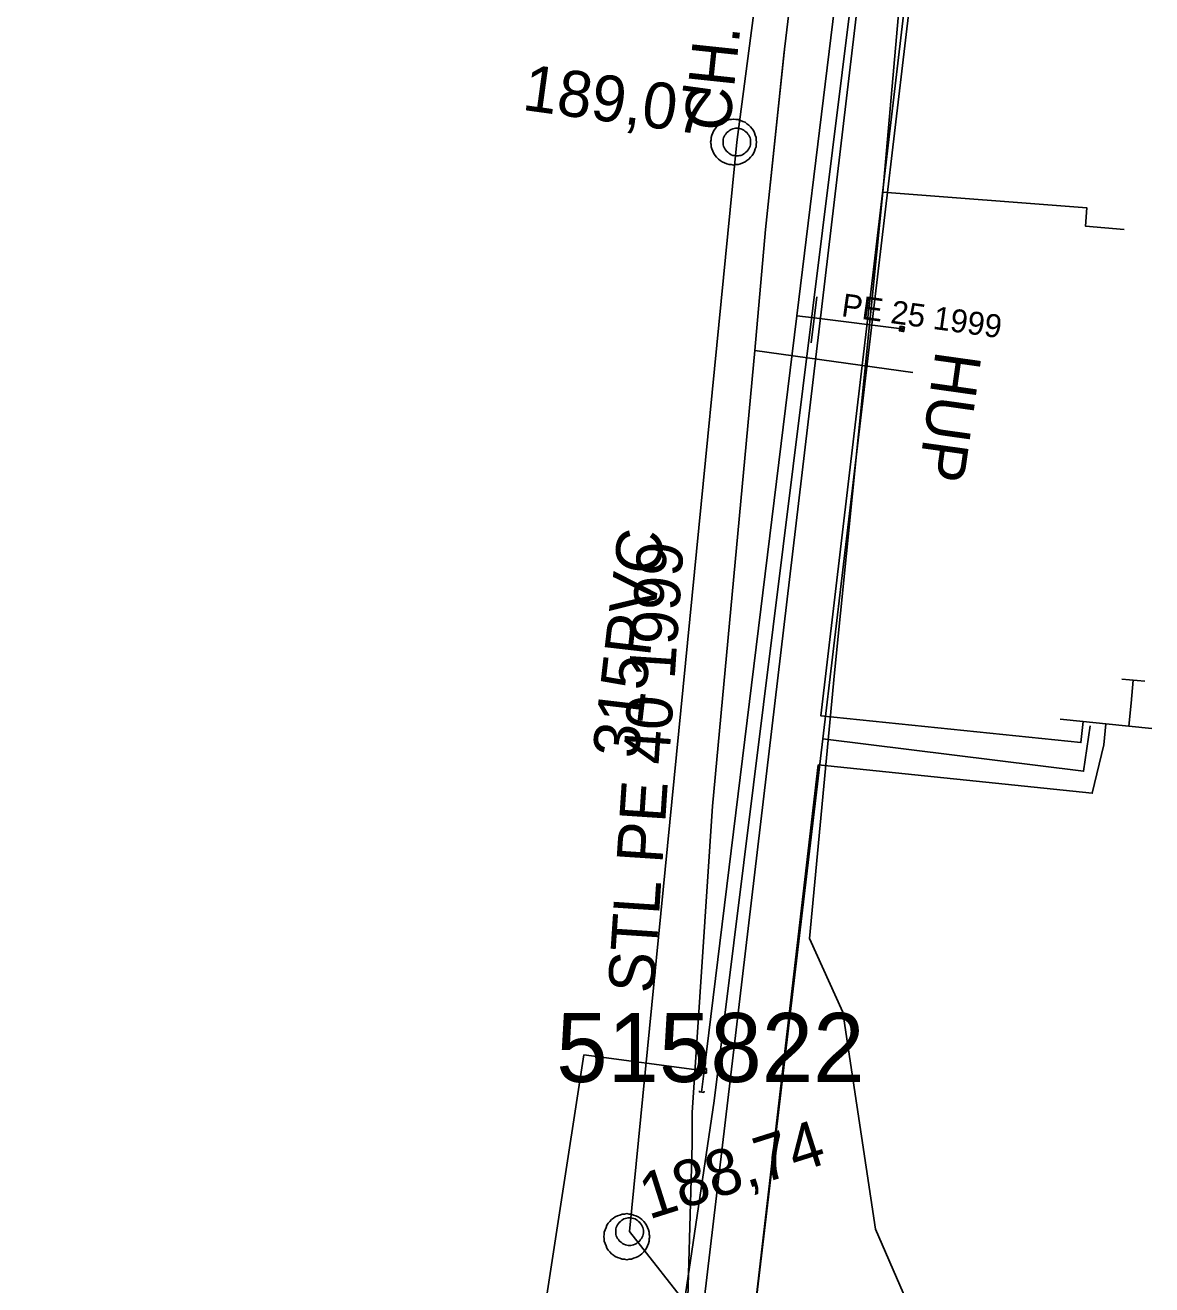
# Model space of a CAD drawing. Extents: x -746464 to -745690, y -1051581 to -1049993.
# Drawn here: x -745945.52 to -745921.06, y -1050962.47 to -1050935.1 of the extents above; entities that cross this region are included whole.
import ezdxf

# ---------------------------------------------------------------- set-up
doc = ezdxf.new("R2010")
doc.units = 0
for name, color, linetype in [('04_CETIN_sdelovaci_podzem', 7, 'Continuous'), ('45_Eltodo_popisy', 7, 'Continuous'), ('45_Eltodo_vedeni_NN_zemni', 7, 'Continuous'), ('48_Prazs_plynarenska_STL', 7, 'Continuous'), ('48_Prazs_plynarenska_STL_chranicka', 7, 'Continuous'), ('48_Prazs_plynarenska_STL_popisy', 7, 'Continuous'), ('51_PVaK_kanal_jednotna_overena poloha_rad', 7, 'Continuous'), ('51_PVaK_kanal_objekty', 7, 'Continuous'), ('51_PVaK_kanal_popisy', 7, 'Continuous'), ('51_PVaK_vodovod_chranicky_objekty', 7, 'Continuous'), ('51_PVaK_vodovod_neoverena poloha_rad', 7, 'Continuous'), ('51_PVaK_vodovod_NEPROVOZUJE PVK_neoverene poloha', 7, 'Continuous'), ('51_PVaK_vodovod_overena poloha_rad', 7, 'Continuous'), ('55_PREdi_NN', 7, 'Continuous'), ('55_PREdi_NN_pripojovaci_misto', 7, 'Continuous')]:
    doc.layers.add(name, color=color, linetype=linetype)

msp = doc.modelspace()

# ---------------------------------------------------------------- linework, layer by layer
at = {"layer": '04_CETIN_sdelovaci_podzem'}
for points in [[(-745926.9, -1050938.73), (-745925.45, -1050922.26), (-745924.92, -1050917.99), (-745924.55, -1050915.62)], [(-745935.44, -1051011.78), (-745933.08, -1050998.46), (-745931.59, -1050985.81), (-745929.11, -1050980.04), (-745927.99, -1050979.19), (-745925.39, -1050979.32), (-745925.27, -1050978.86), (-745922.89, -1050971.35), (-745922.49, -1050970.43), (-745924.73, -1050966.62), (-745927.06, -1050961.26), (-745927.77, -1050956.54), (-745928.49, -1050954.94), (-745927.95, -1050949.17), (-745926.9, -1050938.73)], [(-745926.9, -1050938.73), (-745922.47, -1050939.07), (-745922.5, -1050939.47), (-745921.66, -1050939.54)]]:
    msp.add_lwpolyline(points, dxfattribs=at)
at = {"layer": '45_Eltodo_vedeni_NN_zemni'}
for points in [[(-745930.562, -1050958.466), (-745927.567, -1050934.378)], [(-745933.528, -1050986.207), (-745930.448, -1050965.155), (-745931.301, -1050963.448), (-745930.562, -1050958.466)]]:
    msp.add_lwpolyline(points, dxfattribs=at)
at = {"layer": '48_Prazs_plynarenska_STL'}
for points in [[(-745924.24, -1050897.439), (-745924.39, -1050898.5), (-745926.58, -1050914.43), (-745928.11, -1050927.89), (-745929.03, -1050935.56), (-745929.042, -1050935.678), (-745929.45, -1050939.54), (-745929.68, -1050942.17), (-745930.6, -1050952.07), (-745931.04, -1050958.72), (-745931.04, -1050959.41), (-745931.16, -1050963.77), (-745931.63, -1050972.21), (-745932.22, -1050976.26), (-745932.83, -1050980.22), (-745934.11, -1050987.61), (-745935.84, -1050998.78), (-745937.38, -1051010.18), (-745934.03, -1051011.36), (-745934.04, -1051011.96)], [(-745929.68, -1050942.17), (-745926.248, -1050942.648)]]:
    msp.add_lwpolyline(points, dxfattribs=at)
at = {"layer": '48_Prazs_plynarenska_STL_chranicka'}
msp.add_lwpolyline([(-745929.449, -1050939.539), (-745929.029, -1050935.559)], dxfattribs=at)
at = {"layer": '51_PVaK_kanal_jednotna_overena poloha_rad'}
for p, q in [((-745930.07, -1050937.64), (-745932.4, -1050961.31)), ((-745932.4, -1050961.31), (-745922.1, -1050974.41))]:
    msp.add_line(p, q, dxfattribs=at)
msp.add_lwpolyline([(-745924.23, -1050893.24), (-745924.489, -1050895.205), (-745926.679, -1050911.862), (-745928.844, -1050928.32), (-745930.07, -1050937.64)], dxfattribs=at)
at = {"layer": '51_PVaK_kanal_objekty'}
for points in [[(-745929.64, -1050937.64), (-745929.65, -1050937.59), (-745929.65, -1050937.54), (-745929.67, -1050937.49), (-745929.69, -1050937.44), (-745929.71, -1050937.39), (-745929.74, -1050937.35), (-745929.77, -1050937.31), (-745929.81, -1050937.27), (-745929.85, -1050937.24), (-745929.89, -1050937.21), (-745929.94, -1050937.19), (-745929.99, -1050937.17), (-745930.04, -1050937.15), (-745930.09, -1050937.15), (-745930.14, -1050937.14), (-745930.19, -1050937.15), (-745930.24, -1050937.15), (-745930.29, -1050937.17), (-745930.34, -1050937.19), (-745930.39, -1050937.21), (-745930.43, -1050937.24), (-745930.47, -1050937.27), (-745930.51, -1050937.31), (-745930.54, -1050937.35), (-745930.57, -1050937.39), (-745930.59, -1050937.44), (-745930.61, -1050937.49), (-745930.63, -1050937.54), (-745930.63, -1050937.59), (-745930.64, -1050937.64), (-745930.63, -1050937.69), (-745930.63, -1050937.74), (-745930.61, -1050937.79), (-745930.59, -1050937.84), (-745930.57, -1050937.89), (-745930.54, -1050937.93), (-745930.51, -1050937.97), (-745930.47, -1050938.01), (-745930.43, -1050938.04), (-745930.39, -1050938.07), (-745930.34, -1050938.09), (-745930.29, -1050938.11), (-745930.24, -1050938.13), (-745930.19, -1050938.13), (-745930.14, -1050938.14), (-745930.09, -1050938.13), (-745930.04, -1050938.13), (-745929.99, -1050938.11), (-745929.94, -1050938.09), (-745929.89, -1050938.07), (-745929.85, -1050938.04), (-745929.81, -1050938.01), (-745929.77, -1050937.97), (-745929.74, -1050937.93), (-745929.71, -1050937.89), (-745929.69, -1050937.84), (-745929.67, -1050937.79), (-745929.65, -1050937.74), (-745929.65, -1050937.69), (-745929.64, -1050937.64)], [(-745929.77, -1050937.64), (-745929.77, -1050937.61), (-745929.776, -1050937.58), (-745929.782, -1050937.55), (-745929.794, -1050937.52), (-745929.812, -1050937.49), (-745929.83, -1050937.466), (-745929.848, -1050937.442), (-745929.872, -1050937.418), (-745929.896, -1050937.4), (-745929.92, -1050937.382), (-745929.95, -1050937.364), (-745929.98, -1050937.352), (-745930.01, -1050937.346), (-745930.04, -1050937.34), (-745930.07, -1050937.34), (-745930.1, -1050937.34), (-745930.13, -1050937.346), (-745930.16, -1050937.352), (-745930.19, -1050937.364), (-745930.22, -1050937.382), (-745930.244, -1050937.4), (-745930.268, -1050937.418), (-745930.292, -1050937.442), (-745930.31, -1050937.466), (-745930.328, -1050937.49), (-745930.346, -1050937.52), (-745930.358, -1050937.55), (-745930.364, -1050937.58), (-745930.37, -1050937.61), (-745930.37, -1050937.64), (-745930.37, -1050937.67), (-745930.364, -1050937.7), (-745930.358, -1050937.73), (-745930.346, -1050937.76), (-745930.328, -1050937.79), (-745930.31, -1050937.814), (-745930.292, -1050937.838), (-745930.268, -1050937.862), (-745930.244, -1050937.88), (-745930.22, -1050937.898), (-745930.19, -1050937.916), (-745930.16, -1050937.928), (-745930.13, -1050937.934), (-745930.1, -1050937.94), (-745930.07, -1050937.94), (-745930.04, -1050937.94), (-745930.01, -1050937.934), (-745929.98, -1050937.928), (-745929.95, -1050937.916), (-745929.92, -1050937.898), (-745929.896, -1050937.88), (-745929.872, -1050937.862), (-745929.848, -1050937.838), (-745929.83, -1050937.814), (-745929.812, -1050937.79), (-745929.794, -1050937.76), (-745929.782, -1050937.73), (-745929.776, -1050937.7), (-745929.77, -1050937.67), (-745929.77, -1050937.64)], [(-745931.96, -1050961.42), (-745931.97, -1050961.37), (-745931.97, -1050961.32), (-745931.99, -1050961.27), (-745932.01, -1050961.22), (-745932.03, -1050961.17), (-745932.06, -1050961.13), (-745932.09, -1050961.09), (-745932.13, -1050961.05), (-745932.17, -1050961.02), (-745932.21, -1050960.99), (-745932.26, -1050960.97), (-745932.31, -1050960.95), (-745932.36, -1050960.93), (-745932.41, -1050960.93), (-745932.46, -1050960.92), (-745932.51, -1050960.93), (-745932.56, -1050960.93), (-745932.61, -1050960.95), (-745932.66, -1050960.97), (-745932.71, -1050960.99), (-745932.75, -1050961.02), (-745932.79, -1050961.05), (-745932.83, -1050961.09), (-745932.86, -1050961.13), (-745932.89, -1050961.17), (-745932.91, -1050961.22), (-745932.93, -1050961.27), (-745932.95, -1050961.32), (-745932.95, -1050961.37), (-745932.96, -1050961.42), (-745932.95, -1050961.47), (-745932.95, -1050961.52), (-745932.93, -1050961.57), (-745932.91, -1050961.62), (-745932.89, -1050961.67), (-745932.86, -1050961.71), (-745932.83, -1050961.75), (-745932.79, -1050961.79), (-745932.75, -1050961.82), (-745932.71, -1050961.85), (-745932.66, -1050961.87), (-745932.61, -1050961.89), (-745932.56, -1050961.91), (-745932.51, -1050961.91), (-745932.46, -1050961.92), (-745932.41, -1050961.91), (-745932.36, -1050961.91), (-745932.31, -1050961.89), (-745932.26, -1050961.87), (-745932.21, -1050961.85), (-745932.17, -1050961.82), (-745932.13, -1050961.79), (-745932.09, -1050961.75), (-745932.06, -1050961.71), (-745932.03, -1050961.67), (-745932.01, -1050961.62), (-745931.99, -1050961.57), (-745931.97, -1050961.52), (-745931.97, -1050961.47), (-745931.96, -1050961.42)], [(-745932.1, -1050961.31), (-745932.1, -1050961.28), (-745932.106, -1050961.25), (-745932.112, -1050961.22), (-745932.124, -1050961.19), (-745932.142, -1050961.16), (-745932.16, -1050961.136), (-745932.178, -1050961.112), (-745932.202, -1050961.088), (-745932.226, -1050961.07), (-745932.25, -1050961.052), (-745932.28, -1050961.034), (-745932.31, -1050961.022), (-745932.34, -1050961.016), (-745932.37, -1050961.01), (-745932.4, -1050961.01), (-745932.43, -1050961.01), (-745932.46, -1050961.016), (-745932.49, -1050961.022), (-745932.52, -1050961.034), (-745932.55, -1050961.052), (-745932.574, -1050961.07), (-745932.598, -1050961.088), (-745932.622, -1050961.112), (-745932.64, -1050961.136), (-745932.658, -1050961.16), (-745932.676, -1050961.19), (-745932.688, -1050961.22), (-745932.694, -1050961.25), (-745932.7, -1050961.28), (-745932.7, -1050961.31), (-745932.7, -1050961.34), (-745932.694, -1050961.37), (-745932.688, -1050961.4), (-745932.676, -1050961.43), (-745932.658, -1050961.46), (-745932.64, -1050961.484), (-745932.622, -1050961.508), (-745932.598, -1050961.532), (-745932.574, -1050961.55), (-745932.55, -1050961.568), (-745932.52, -1050961.586), (-745932.49, -1050961.598), (-745932.46, -1050961.604), (-745932.43, -1050961.61), (-745932.4, -1050961.61), (-745932.37, -1050961.61), (-745932.34, -1050961.604), (-745932.31, -1050961.598), (-745932.28, -1050961.586), (-745932.25, -1050961.568), (-745932.226, -1050961.55), (-745932.202, -1050961.532), (-745932.178, -1050961.508), (-745932.16, -1050961.484), (-745932.142, -1050961.46), (-745932.124, -1050961.43), (-745932.112, -1050961.4), (-745932.106, -1050961.37), (-745932.1, -1050961.34), (-745932.1, -1050961.31)]]:
    msp.add_lwpolyline(points, dxfattribs=at)
at = {"layer": '51_PVaK_vodovod_chranicky_objekty'}
for p, q in [((-745928.458, -1050942), (-745928.332, -1050941)), ((-745926.543, -1050941.742), (-745926.431, -1050941.655)), ((-745926.531, -1050941.643), (-745926.533, -1050941.663)), ((-745926.531, -1050941.643), (-745926.444, -1050941.754)), ((-745926.531, -1050941.643), (-745926.511, -1050941.645)), ((-745926.431, -1050941.655), (-745926.451, -1050941.653)), ((-745926.431, -1050941.655), (-745926.434, -1050941.675)), ((-745926.543, -1050941.742), (-745926.541, -1050941.722)), ((-745926.543, -1050941.742), (-745926.523, -1050941.744)), ((-745926.444, -1050941.754), (-745926.464, -1050941.752)), ((-745926.444, -1050941.754), (-745926.441, -1050941.735)), ((-745930.829, -1050957.869), (-745930.729, -1050957.769)), ((-745930.829, -1050957.769), (-745930.729, -1050957.869)), ((-745930.829, -1050957.769), (-745930.829, -1050957.789)), ((-745930.829, -1050957.769), (-745930.809, -1050957.769)), ((-745930.729, -1050957.769), (-745930.749, -1050957.769)), ((-745930.729, -1050957.769), (-745930.729, -1050957.789)), ((-745930.829, -1050957.869), (-745930.829, -1050957.849)), ((-745930.829, -1050957.869), (-745930.809, -1050957.869)), ((-745930.729, -1050957.869), (-745930.749, -1050957.869)), ((-745930.729, -1050957.869), (-745930.729, -1050957.849))]:
    msp.add_line(p, q, dxfattribs=at)
for points in [[(-745926.438, -1050941.705), (-745926.437, -1050941.7), (-745926.437, -1050941.695), (-745926.438, -1050941.69), (-745926.439, -1050941.685), (-745926.441, -1050941.679), (-745926.444, -1050941.675), (-745926.446, -1050941.671), (-745926.45, -1050941.666), (-745926.453, -1050941.663), (-745926.457, -1050941.659), (-745926.462, -1050941.655), (-745926.466, -1050941.653), (-745926.471, -1050941.651), (-745926.476, -1050941.65), (-745926.481, -1050941.649), (-745926.486, -1050941.648), (-745926.491, -1050941.649), (-745926.496, -1050941.649), (-745926.501, -1050941.65), (-745926.507, -1050941.653), (-745926.511, -1050941.655), (-745926.515, -1050941.658), (-745926.52, -1050941.661), (-745926.523, -1050941.665), (-745926.527, -1050941.668), (-745926.53, -1050941.673), (-745926.533, -1050941.678), (-745926.535, -1050941.683), (-745926.536, -1050941.687), (-745926.537, -1050941.692), (-745926.537, -1050941.697), (-745926.537, -1050941.702), (-745926.537, -1050941.708), (-745926.535, -1050941.713), (-745926.533, -1050941.718), (-745926.53, -1050941.722), (-745926.528, -1050941.727), (-745926.525, -1050941.731), (-745926.521, -1050941.735), (-745926.517, -1050941.738), (-745926.513, -1050941.742), (-745926.508, -1050941.744), (-745926.503, -1050941.746), (-745926.498, -1050941.748), (-745926.493, -1050941.748), (-745926.488, -1050941.749), (-745926.483, -1050941.748), (-745926.478, -1050941.748), (-745926.473, -1050941.747), (-745926.468, -1050941.744), (-745926.463, -1050941.742), (-745926.459, -1050941.739), (-745926.455, -1050941.736), (-745926.451, -1050941.732), (-745926.448, -1050941.729), (-745926.444, -1050941.724), (-745926.441, -1050941.72), (-745926.44, -1050941.715), (-745926.438, -1050941.71), (-745926.438, -1050941.705)], [(-745930.729, -1050957.819), (-745930.729, -1050957.814), (-745930.73, -1050957.809), (-745930.731, -1050957.804), (-745930.733, -1050957.799), (-745930.736, -1050957.794), (-745930.739, -1050957.79), (-745930.742, -1050957.786), (-745930.746, -1050957.782), (-745930.75, -1050957.779), (-745930.754, -1050957.776), (-745930.759, -1050957.773), (-745930.764, -1050957.771), (-745930.769, -1050957.77), (-745930.774, -1050957.769), (-745930.779, -1050957.769), (-745930.784, -1050957.769), (-745930.789, -1050957.77), (-745930.794, -1050957.771), (-745930.799, -1050957.773), (-745930.804, -1050957.776), (-745930.808, -1050957.779), (-745930.812, -1050957.782), (-745930.816, -1050957.786), (-745930.819, -1050957.79), (-745930.822, -1050957.794), (-745930.825, -1050957.799), (-745930.827, -1050957.804), (-745930.828, -1050957.809), (-745930.829, -1050957.814), (-745930.829, -1050957.819), (-745930.829, -1050957.824), (-745930.828, -1050957.829), (-745930.827, -1050957.834), (-745930.825, -1050957.839), (-745930.822, -1050957.844), (-745930.819, -1050957.848), (-745930.816, -1050957.852), (-745930.812, -1050957.856), (-745930.808, -1050957.859), (-745930.804, -1050957.862), (-745930.799, -1050957.865), (-745930.794, -1050957.867), (-745930.789, -1050957.868), (-745930.784, -1050957.869), (-745930.779, -1050957.869), (-745930.774, -1050957.869), (-745930.769, -1050957.868), (-745930.764, -1050957.867), (-745930.759, -1050957.865), (-745930.754, -1050957.862), (-745930.75, -1050957.859), (-745930.746, -1050957.856), (-745930.742, -1050957.852), (-745930.739, -1050957.848), (-745930.736, -1050957.844), (-745930.733, -1050957.839), (-745930.731, -1050957.834), (-745930.73, -1050957.829), (-745930.729, -1050957.824), (-745930.729, -1050957.819)], [(-745930.78, -1050958.262), (-745930.783, -1050958.287), (-745930.883, -1050958.276), (-745930.88, -1050958.251)]]:
    msp.add_lwpolyline(points, dxfattribs=at)
at = {"layer": '51_PVaK_vodovod_neoverena poloha_rad'}
msp.add_line((-745930.78, -1050957.82), (-745930.834, -1050958.281), dxfattribs=at)
at = {"layer": '51_PVaK_vodovod_NEPROVOZUJE PVK_neoverene poloha'}
for p, q in [((-745928.771, -1050941.412), (-745928.39, -1050941.46)), ((-745928.39, -1050941.46), (-745926.488, -1050941.7))]:
    msp.add_line(p, q, dxfattribs=at)
msp.add_lwpolyline([(-745930.78, -1050957.82), (-745928.771, -1050941.412), (-745926.792, -1050925.245), (-745924.145, -1050903.624)], dxfattribs=at)
at = {"layer": '51_PVaK_vodovod_overena poloha_rad'}
msp.add_lwpolyline([(-745930.78, -1050957.82), (-745933.39, -1050957.47), (-745935.02, -1050968.05), (-745936.34, -1050978.19), (-745938.53, -1050992.87), (-745941.27, -1051010.72), (-745942.84, -1051021.08), (-745945.52, -1051023.03)], dxfattribs=at)
at = {"layer": '55_PREdi_NN'}
for points in [[(-745925.944, -1050974.322), (-745925.439, -1050973.802), (-745929.534, -1050967.465), (-745931.161, -1050966.035), (-745923.087, -1050897.794), (-745922.052, -1050897.675), (-745921.205, -1050897.823)], [(-745921.446, -1050897.706), (-745922.223, -1050897.847), (-745924.087, -1050915.752), (-745925.959, -1050931.626), (-745928.205, -1050950.605)], [(-745922.906, -1050912.389), (-745923.788, -1050912.286), (-745928.245, -1050950.106), (-745922.601, -1050950.687), (-745922.554, -1050950.226)], [(-745921.559, -1050950.327), (-745921.508, -1050949.83)], [(-745923.051, -1050950.175), (-745922.554, -1050950.226), (-745922.056, -1050950.276), (-745921.559, -1050950.327), (-745921.061, -1050950.378)], [(-745922.056, -1050950.276), (-745922.103, -1050950.737), (-745922.354, -1050951.788), (-745928.301, -1050951.171), (-745929.975, -1050965.56), (-745929.401, -1050966.13)], [(-745928.205, -1050950.605), (-745922.541, -1050951.309), (-745922.4, -1050950.32)], [(-745932.338, -1051022.282), (-745932.127, -1051008.162), (-745931.416, -1050993.444), (-745929.063, -1050979.386), (-745924.123, -1050973.879), (-745928.821, -1050966.705), (-745929.975, -1050965.56), (-745928.205, -1050950.605)]]:
    msp.add_lwpolyline(points, dxfattribs=at)
at = {"layer": '55_PREdi_NN_pripojovaci_misto'}
for p, q in [((-745921.215, -1050949.354), (-745921.713, -1050949.31)), ((-745921.508, -1050949.83), (-745921.464, -1050949.332))]:
    msp.add_line(p, q, dxfattribs=at)

# ---------------------------------------------------------------- texts
at = {"layer": '45_Eltodo_popisy'}
msp.add_text('515822', height=1.5, dxfattribs=at).set_placement((-745933.991, -1050958.06))
at = {"layer": '48_Prazs_plynarenska_STL_popisy'}
for s, height, rotation, p in [('CH. PE 63 4', 1, 83.976, (-745930.232, -1050937.434)), ('PE 25 1999', 0.5, 352.071, (-745927.817, -1050941.42)), ('HUP', 1, 262, (-745925.748, -1050942.148)), ('STL PE 40 1999', 1, 86.2145, (-745931.872, -1050956.15))]:
    msp.add_text(s, height=height, rotation=rotation, dxfattribs=at).set_placement(p)
at = {"layer": '51_PVaK_kanal_popisy'}
for s, rotation, p in [('189,07', 352.1898, (-745934.752, -1050936.937)), ('315PVC', 83.3781, (-745932.215, -1050951.053)), ('188,74', 17.5811, (-745931.983, -1050961.052))]:
    msp.add_text(s, height=1, rotation=rotation, dxfattribs=at).set_placement(p)

doc.saveas('drawing.dxf')
